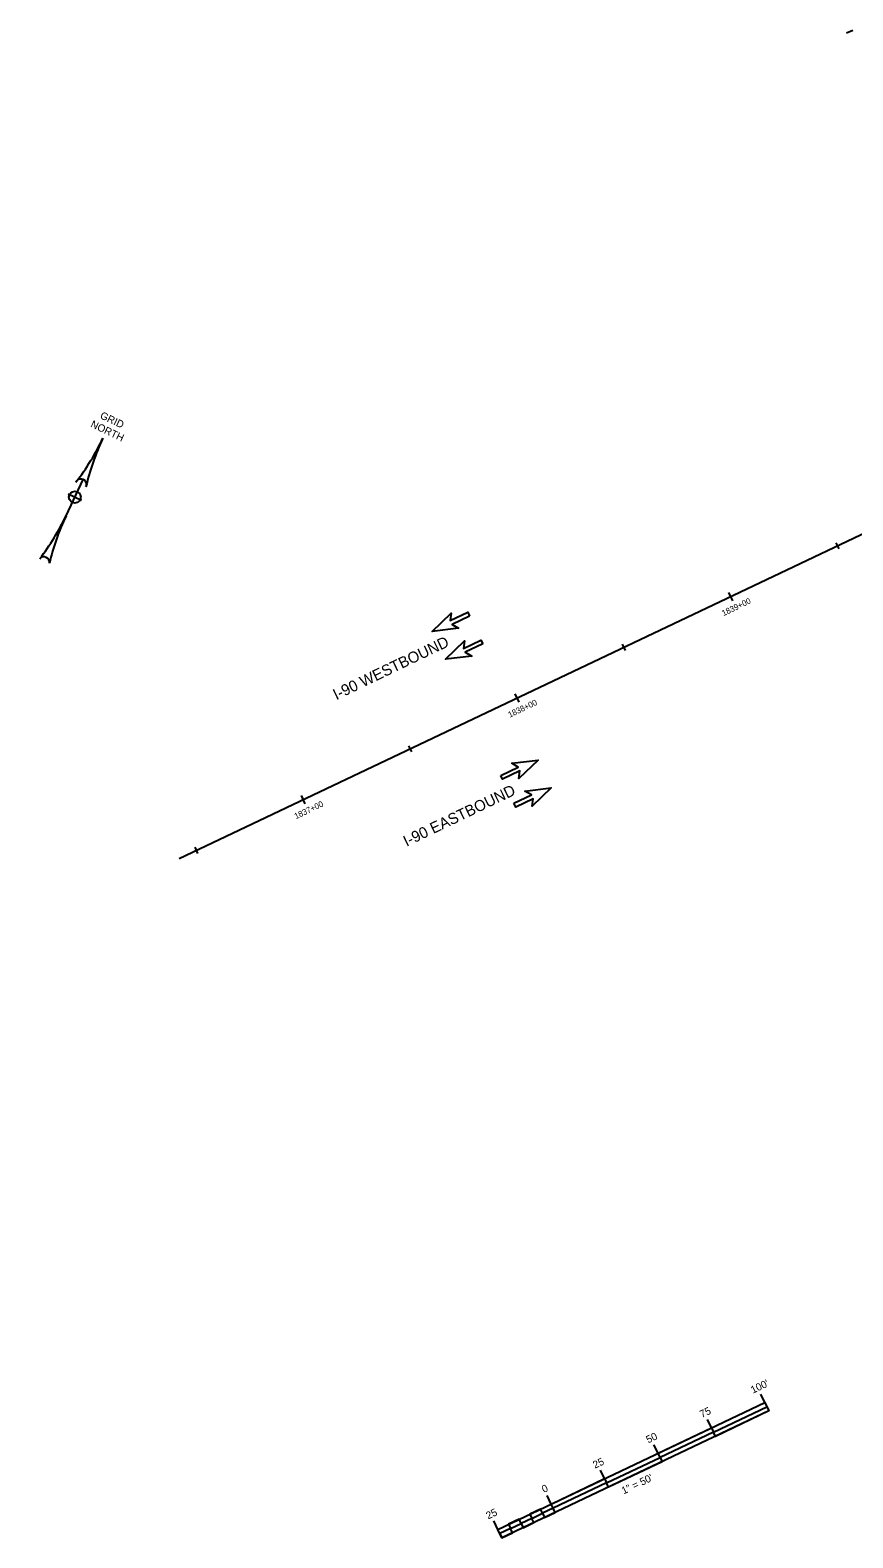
# Model space of a CAD drawing. Extents: x 1162151 to 1163042, y 1142576 to 1143214.
# Drawn here: x 1162151 to 1162498, y 1142576 to 1143214 of the extents above; entities that cross this region are included whole.
import ezdxf

# ---------------------------------------------------------------- set-up
doc = ezdxf.new("R2010")
doc.units = 0
for name, color, linetype in [('GSCOLORFILL', 7, 'Continuous'), ('NDEFAULT_P_T', 7, 'Continuous'), ('O_Details_Dimensions_Extension_Lines_P', 7, 'Continuous'), ('O_Details_Text Normal Proposed_P_T', 7, 'Continuous'), ('O_Details_User Level 1_P', 7, 'Continuous'), ('SHEET_BORDER', 7, 'Continuous'), ('SHEET_BORDER_CUT', 7, 'Continuous'), ('SHEET_BORDER_TEXT', 7, 'Continuous'), ('SHEET_BORDER_TEXT_SHEETINFO', 7, 'Continuous')]:
    doc.layers.add(name, color=color, linetype=linetype)

# ---------------------------------------------------------------- blocks, each defined once
blk = doc.blocks.new('NNAG')
at = {"layer": 'O_Details_User Level 1_P'}
for p, q in [((0, -0.01323), (0, 0.01254)), ((-0.00486, 0), (0.00462, 0))]:
    blk.add_line(p, q, dxfattribs=at)
blk.add_circle((-0.00005, 0.00004), 0.00378, dxfattribs=at)
for centre, radius, start, end in [((-0.15227, 0.04159), 0.15226, 347.65235, 0.1148), ((0.15226, 0.04159), 0.15226, 179.8852, 192.34765), ((0, 0.00903), 0.00352, 0, 180), ((-0.15227, -0.01327), 0.15226, 347.89252, 0.0168), ((0.15226, -0.01327), 0.15226, 179.9832, 192.10748), ((-0.00001, -0.04618), 0.00352, 15.89482, 164.10609)]:
    blk.add_arc(centre, radius, start, end, dxfattribs=at)
for s, p in [('NORTH', (-0.01072, 0.04497)), ('GRID', (-0.00765, 0.05259))]:
    blk.add_text(s, height=0.004757, dxfattribs=at).set_placement(p)

msp = doc.modelspace()

# ---------------------------------------------------------------- linework, layer by layer
at = {"layer": 'GSCOLORFILL'}
msp.add_line((1162213.43, 1142863.58), (1162911.07, 1143195.18), dxfattribs=at)
at = {"layer": 'O_Details_Dimensions_Extension_Lines_P'}
for points in [[(1162495.47, 1143212.7), (1162498.1, 1143213.88)], [(1162490.99, 1142997.1), (1162492.22, 1142994.5)], [(1162445.62, 1142976.07), (1162447.27, 1142972.6)], [(1162400.67, 1142954.17), (1162401.91, 1142951.57)], [(1162355.31, 1142933.14), (1162356.96, 1142929.67)], [(1162310.35, 1142911.25), (1162311.59, 1142908.64)], [(1162264.99, 1142890.21), (1162266.64, 1142886.75)], [(1162220.04, 1142868.32), (1162221.27, 1142865.72)]]:
    msp.add_lwpolyline(points, dxfattribs=at)
at = {"layer": 'SHEET_BORDER_CUT'}
for p, q in [((1162460.97, 1142633.5), (1162459.27, 1142637.07)), ((1162438.39, 1142622.77), (1162436.69, 1142626.34)), ((1162415.81, 1142612.03), (1162414.11, 1142615.61)), ((1162393.23, 1142601.3), (1162391.53, 1142604.88)), ((1162370.65, 1142590.57), (1162368.95, 1142594.15)), ((1162348.07, 1142579.84), (1162346.37, 1142583.41))]:
    msp.add_line(p, q, dxfattribs=at)
for points in [[(1162348.07, 1142579.84), (1162460.97, 1142633.5), (1162462.67, 1142629.92), (1162349.77, 1142576.26)], [(1162439.24, 1142620.98), (1162461.82, 1142631.71), (1162462.67, 1142629.92), (1162440.09, 1142619.19)], [(1162415.81, 1142612.03), (1162438.39, 1142622.77), (1162439.24, 1142620.98), (1162416.66, 1142610.25)], [(1162394.08, 1142599.51), (1162416.66, 1142610.25), (1162417.51, 1142608.46), (1162394.93, 1142597.73)], [(1162370.65, 1142590.57), (1162393.23, 1142601.3), (1162394.08, 1142599.51), (1162371.5, 1142588.78)], [(1162357.1, 1142584.13), (1162352.58, 1142581.98), (1162353.43, 1142580.2), (1162357.95, 1142582.34)], [(1162362.47, 1142584.49), (1162357.95, 1142582.34), (1162358.8, 1142580.55), (1162363.32, 1142582.7)], [(1162366.13, 1142588.42), (1162361.62, 1142586.28), (1162362.47, 1142584.49), (1162366.98, 1142586.63)], [(1162371.5, 1142588.78), (1162366.98, 1142586.63), (1162367.83, 1142584.85), (1162372.35, 1142586.99)], [(1162353.43, 1142580.2), (1162348.92, 1142578.05), (1162349.77, 1142576.26), (1162354.28, 1142578.41)]]:
    msp.add_lwpolyline(points, close=True, dxfattribs=at)
at = {"layer": 'SHEET_BORDER_TEXT_SHEETINFO'}
for points in [[(1162336.18, 1142966.08), (1162328.77, 1142962.56), (1162331.52, 1142960.92), (1162320.39, 1142959.55), (1162328.47, 1142967.32), (1162328.01, 1142964.16), (1162335.42, 1142967.68)], [(1162341.76, 1142954.34), (1162334.35, 1142950.82), (1162337.1, 1142949.18), (1162325.97, 1142947.81), (1162334.05, 1142955.58), (1162333.59, 1142952.42), (1162341, 1142955.94)], [(1162349.33, 1142898.68), (1162356.73, 1142902.2), (1162353.99, 1142903.84), (1162365.11, 1142905.21), (1162357.03, 1142897.44), (1162357.49, 1142900.6), (1162350.09, 1142897.08)], [(1162354.91, 1142886.94), (1162362.31, 1142890.46), (1162359.57, 1142892.1), (1162370.69, 1142893.47), (1162362.61, 1142885.7), (1162363.07, 1142888.86), (1162355.67, 1142885.34)]]:
    msp.add_lwpolyline(points, close=True, dxfattribs=at)

# ---------------------------------------------------------------- block references
at = {"layer": 'NDEFAULT_P_T', "xscale": 660, "yscale": 660, "rotation": -25.42217353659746}
msp.add_blockref('NNAG', (1162169.41, 1143016.35), dxfattribs=at)

# ---------------------------------------------------------------- texts
at = {"layer": 'O_Details_Text Normal Proposed_P_T'}
for s, p in [('1839+00', (1162443.48, 1142966.01)), ('1838+00', (1162353.16, 1142923.08)), ('1837+00', (1162262.84, 1142880.15))]:
    msp.add_text(s, height=2.501, rotation=25.42217, dxfattribs=at).set_placement(p)
at = {"layer": 'SHEET_BORDER'}
for s, p in [('I-90 WESTBOUND', (1162279.87, 1142930.48)), ('I-90 EASTBOUND', (1162309.53, 1142868.47))]:
    msp.add_text(s, height=4.692, rotation=25.63701, dxfattribs=at).set_placement(p)
at = {"layer": 'SHEET_BORDER_TEXT'}
for s, height, p in [("100'", 3.126, (1162455.9, 1142637.2)), ('75', 3.126, (1162434.34, 1142626.95)), ('50', 3.126, (1162411.67, 1142616.18)), ('25', 3.126, (1162389.18, 1142605.49)), ('1" = 50\'', 3.126, (1162401.28, 1142594.58)), ('0', 3.13, (1162367.57, 1142595.22)), ('25', 3.126, (1162344.02, 1142584.02))]:
    msp.add_text(s, height=height, rotation=25.42217, dxfattribs=at).set_placement(p)

doc.saveas('drawing.dxf')
